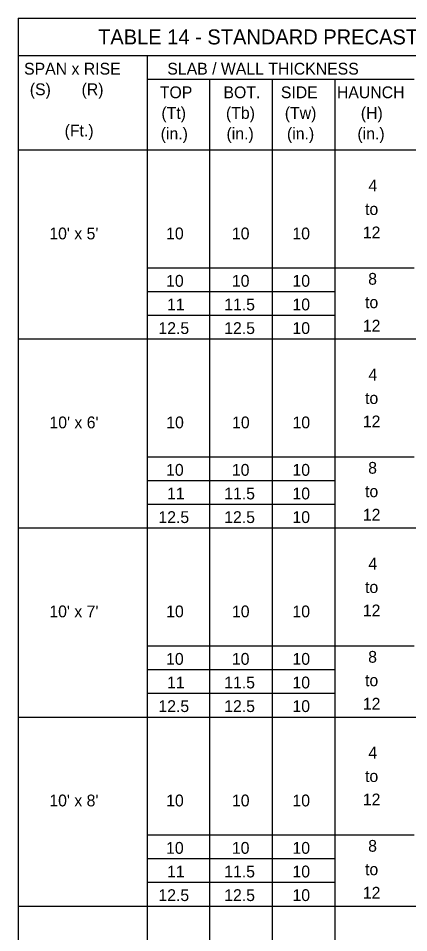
# Model space of a CAD drawing. Extents: x 10351.18 to 10353.4, y 76371.55 to 76372.62.
# Drawn here: x 10351.1919 to 10351.4001, y 76372.0471 to 76372.5347 of the extents above; entities that cross this region are included whole.
import ezdxf

# ---------------------------------------------------------------- set-up
doc = ezdxf.new("R2010")
doc.units = 0
doc.layers.add('AdhocPoint_dp', color=7, linetype='Continuous')
doc.layers.add('PlotBorder_dp', color=7, linetype='Continuous')

msp = doc.modelspace()

# ---------------------------------------------------------------- linework, layer by layer
at = {"layer": 'PlotBorder_dp'}
for p, q in [((10351.19191, 76372.53475), (10351.19191, 76371.85973)), ((10351.19191, 76372.53475), (10351.78665, 76372.53475)), ((10351.19191, 76372.51488), (10351.78665, 76372.51488)), ((10351.26055, 76372.51488), (10351.26055, 76371.85973)), ((10351.26055, 76372.50228), (10351.40299, 76372.50228)), ((10351.29391, 76372.50228), (10351.29391, 76371.85973)), ((10351.32727, 76372.50228), (10351.32727, 76371.85973)), ((10351.36063, 76372.50228), (10351.36063, 76371.85973)), ((10351.19191, 76372.46453), (10351.78665, 76372.46453)), ((10351.40299, 76372.40153), (10351.26055, 76372.40153)), ((10351.36063, 76372.38893), (10351.26055, 76372.38893)), ((10351.36063, 76372.37633), (10351.26055, 76372.37633)), ((10351.19191, 76372.36373), (10351.70926, 76372.36373)), ((10351.40299, 76372.30073), (10351.26055, 76372.30073)), ((10351.36063, 76372.28813), (10351.26055, 76372.28813)), ((10351.36063, 76372.27553), (10351.26055, 76372.27553)), ((10351.19191, 76372.26293), (10351.70926, 76372.26293)), ((10351.40299, 76372.19993), (10351.26055, 76372.19993)), ((10351.36063, 76372.18733), (10351.26055, 76372.18733)), ((10351.36063, 76372.17473), (10351.26055, 76372.17473)), ((10351.19191, 76372.16213), (10351.70926, 76372.16213)), ((10351.40299, 76372.09913), (10351.26055, 76372.09913)), ((10351.36063, 76372.08653), (10351.26055, 76372.08653)), ((10351.36063, 76372.07393), (10351.26055, 76372.07393)), ((10351.19191, 76372.06133), (10351.70926, 76372.06133))]:
    msp.add_line(p, q, dxfattribs=at)

# ---------------------------------------------------------------- texts
at = {"layer": 'AdhocPoint_dp'}
for s, height, p in [('TABLE 14 - STANDARD PRECAST BOX CULVERT DESIGNS (3" COVER) - 10\' SPANS', 0.008, (10351.23445, 76372.52081)), ('SLAB / WALL THICKNESS', 0.0063, (10351.27137, 76372.50472)), ("10' x 5'", 0.0063, (10351.20845, 76372.41685)), ('10', 0.0063, (10351.27072, 76372.41685)), ('10', 0.0063, (10351.30581, 76372.41685)), ('10', 0.0063, (10351.33805, 76372.41685)), ('10', 0.0063, (10351.27071, 76372.39158)), ('10', 0.0063, (10351.3058, 76372.39158)), ('10', 0.0063, (10351.33809, 76372.39158)), ('11', 0.0063, (10351.27123, 76372.37898)), ('11.5', 0.0063, (10351.3017, 76372.37898)), ('10', 0.0063, (10351.33809, 76372.37898)), ('12.5', 0.0063, (10351.26661, 76372.36638)), ('12.5', 0.0063, (10351.30171, 76372.36638)), ('10', 0.0063, (10351.33809, 76372.36638)), ('10', 0.0063, (10351.27071, 76372.29078)), ('10', 0.0063, (10351.3058, 76372.29078)), ('10', 0.0063, (10351.33809, 76372.29078)), ('11', 0.0063, (10351.27123, 76372.27818)), ('11.5', 0.0063, (10351.3017, 76372.27818)), ('10', 0.0063, (10351.33809, 76372.27818)), ('12.5', 0.0063, (10351.26661, 76372.26558)), ('12.5', 0.0063, (10351.30171, 76372.26558)), ('10', 0.0063, (10351.33809, 76372.26558)), ('10', 0.0063, (10351.27071, 76372.18998)), ('10', 0.0063, (10351.3058, 76372.18998)), ('10', 0.0063, (10351.33809, 76372.18998)), ('11', 0.0063, (10351.27123, 76372.17738)), ('11.5', 0.0063, (10351.3017, 76372.17738)), ('10', 0.0063, (10351.33809, 76372.17738)), ('12.5', 0.0063, (10351.26661, 76372.16478)), ('12.5', 0.0063, (10351.30171, 76372.16478)), ('10', 0.0063, (10351.33809, 76372.16478)), ('10', 0.0063, (10351.27071, 76372.08918)), ('10', 0.0063, (10351.3058, 76372.08918)), ('10', 0.0063, (10351.33809, 76372.08918)), ('11', 0.0063, (10351.27123, 76372.07658)), ('11.5', 0.0063, (10351.3017, 76372.07658)), ('10', 0.0063, (10351.33809, 76372.07658)), ('12.5', 0.0063, (10351.26661, 76372.06398)), ('12.5', 0.0063, (10351.30171, 76372.06398)), ('10', 0.0063, (10351.3381, 76372.06398))]:
    msp.add_text(s, height=height, dxfattribs=at).set_placement(p)
at = {"layer": 'PlotBorder_dp'}
for s, p in [('SPAN x RISE', (10351.195, 76372.50472)), ('(S)       (R)', (10351.19804, 76372.49372)), ('TOP', (10351.26737, 76372.49212)), ('BOT.', (10351.3013, 76372.49212)), ('SIDE', (10351.3319, 76372.49212)), ('HAUNCH', (10351.36179, 76372.49212)), ('(Tt)', (10351.26822, 76372.48112)), ('(Tb)', (10351.30264, 76372.48112)), ('(Tw)', (10351.334, 76372.48112)), ('(H)', (10351.37453, 76372.48112)), ('(Ft.)', (10351.21662, 76372.47172)), ('(in.)', (10351.26783, 76372.47012)), ('(in.)', (10351.30292, 76372.47012)), ('(in.)', (10351.33516, 76372.47012)), ('(in.)', (10351.37272, 76372.47012)), ('4', (10351.37857, 76372.44238)), ('to', (10351.37679, 76372.42988)), ('12', (10351.37562, 76372.41738)), ('8', (10351.37846, 76372.39266)), ('to', (10351.37679, 76372.38016)), ('12', (10351.37562, 76372.36766)), ('4', (10351.37857, 76372.34158)), ('to', (10351.37679, 76372.32908)), ("10' x 6'", (10351.20852, 76372.31607)), ('10', (10351.2708, 76372.31607)), ('10', (10351.30589, 76372.31607)), ('10', (10351.33813, 76372.31607)), ('12', (10351.37562, 76372.31658)), ('8', (10351.37846, 76372.29186)), ('to', (10351.37679, 76372.27936)), ('12', (10351.37562, 76372.26686)), ('4', (10351.37857, 76372.24078)), ('to', (10351.37679, 76372.22828)), ("10' x 7'", (10351.20847, 76372.21529)), ('10', (10351.27075, 76372.21529)), ('10', (10351.30584, 76372.21529)), ('10', (10351.33808, 76372.21529)), ('12', (10351.37562, 76372.21578)), ('8', (10351.37846, 76372.19106)), ('to', (10351.37679, 76372.17856)), ('12', (10351.37562, 76372.16606)), ('4', (10351.37857, 76372.13998)), ('to', (10351.37679, 76372.12748)), ("10' x 8'", (10351.20847, 76372.11446)), ('10', (10351.27075, 76372.11446)), ('10', (10351.30584, 76372.11446)), ('10', (10351.33808, 76372.11446)), ('12', (10351.37562, 76372.11498)), ('8', (10351.37846, 76372.09026)), ('to', (10351.37679, 76372.07776)), ('12', (10351.37562, 76372.06526))]:
    msp.add_text(s, height=0.0063, dxfattribs=at).set_placement(p)

doc.saveas('drawing.dxf')
